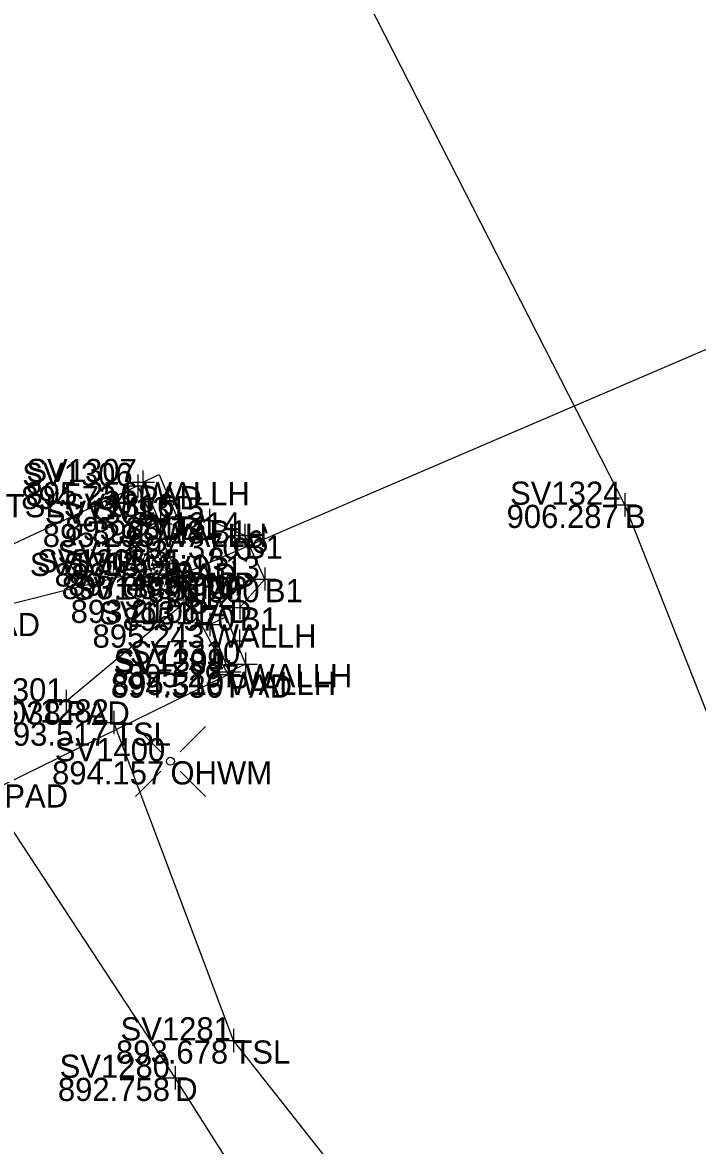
# Model space of a CAD drawing. Extents: x 1918148 to 1919797, y 624701 to 627089.
# Drawn here: x 1918905.66 to 1918934.77, y 625559.4 to 625607.83 of the extents above; entities that cross this region are included whole.
import ezdxf

# ---------------------------------------------------------------- set-up
doc = ezdxf.new("R2010")
doc.units = 0
for name, color, linetype in [('DR_X_Ditch', 7, 'Continuous'), ('DR_X_Elev_Flow', 7, 'Continuous'), ('DR_X_Erosion_Control', 7, 'Continuous'), ('DR_X_Headwall', 7, 'Continuous'), ('DR_X_Storm_Sewer', 7, 'Continuous'), ('DT_X_Break_Line', 7, 'Continuous'), ('SC_Scratch1', 7, 'Continuous'), ('SV_X_Break_Lines', 7, 'Continuous'), ('SV_X_Control_Cells_Found', 7, 'Continuous'), ('SV_X_Shot_Marker', 7, 'Continuous'), ('SV_X_Text_Comment', 7, 'Continuous'), ('SV_X_Text_Elevation', 7, 'Continuous'), ('SV_X_Text_Name', 7, 'Continuous'), ('SV_X_Toe_of_Slope', 7, 'Continuous')]:
    doc.layers.add(name, color=color, linetype=linetype)

msp = doc.modelspace()

# ---------------------------------------------------------------- linework, layer by layer
at = {"layer": 'DR_X_Ditch'}
msp.add_lwpolyline([(1919022.603, 625413.065), (1918990.744, 625447.13), (1918963.473, 625485.28), (1918945.141, 625512.5), (1918919.457, 625550.942), (1918912.249, 625562.326), (1918904.466, 625574.16)], dxfattribs=at)
at = {"layer": 'DR_X_Elev_Flow'}
for p, q in [((1918912.397, 625584.466), (1918912.397, 625583.466)), ((1918912.709, 625584.612), (1918912.709, 625583.612)), ((1918911.897, 625583.966), (1918912.897, 625583.966)), ((1918912.209, 625584.112), (1918913.209, 625584.112)), ((1918912.397, 625583.966), (1918912.397, 625583.966)), ((1918912.709, 625584.112), (1918912.709, 625584.112))]:
    msp.add_line(p, q, dxfattribs=at)
at = {"layer": 'DR_X_Erosion_Control'}
msp.add_lwpolyline([(1918914.537, 625579.717), (1918912.802, 625582.939), (1918912.152, 625584.51), (1918910.641, 625587.846), (1918901.249, 625583.469), (1918899.232, 625582.581), (1918884.997, 625575.988), (1918882.345, 625574.796), (1918883.679, 625571.168), (1918884.991, 625567.785), (1918885.817, 625565.746), (1918890.03, 625568.23), (1918902.973, 625574.056), (1918904.88, 625574.98)], close=True, dxfattribs=at)
at = {"layer": 'DR_X_Headwall'}
for p, q in [((1918910.859, 625588.015), (1918911.556, 625588.347)), ((1918911.556, 625588.347), (1918912.307, 625586.546)), ((1918911.61, 625586.214), (1918910.859, 625588.015)), ((1918912.307, 625586.546), (1918911.61, 625586.214)), ((1918911.61, 625586.214), (1918911.61, 625586.214)), ((1918913.735, 625581.873), (1918914.432, 625582.205)), ((1918914.432, 625582.205), (1918915.276, 625580.164)), ((1918914.579, 625579.832), (1918913.735, 625581.873)), ((1918913.735, 625581.873), (1918913.735, 625581.873)), ((1918913.735, 625581.873), (1918913.735, 625581.873)), ((1918913.735, 625581.873), (1918914.579, 625579.832)), ((1918914.579, 625579.832), (1918913.735, 625581.873)), ((1918915.276, 625580.164), (1918914.579, 625579.832)), ((1918915.276, 625580.164), (1918915.276, 625580.164)), ((1918915.276, 625580.164), (1918915.276, 625580.164)), ((1918914.579, 625579.832), (1918914.579, 625579.832))]:
    msp.add_line(p, q, dxfattribs=at)
at = {"layer": 'DR_X_Storm_Sewer'}
msp.add_line((1918912.397, 625583.966), (1919031.605, 625635.224), dxfattribs=at)
at = {"layer": 'DT_X_Break_Line'}
for p, q in [((1918912.152, 625584.51), (1918903.671, 625582.37)), ((1918912.802, 625582.939), (1918907.541, 625578.556))]:
    msp.add_line(p, q, dxfattribs=at)
at = {"layer": 'SV_X_Break_Lines'}
for points in [[(1919045.664, 625427.604), (1919011.531, 625464.068), (1918983.19, 625498.777), (1918965.767, 625524.183), (1918940.24, 625565.262), (1918931.639, 625587.035), (1918915.781, 625618.093), (1918902.808, 625643.724), (1918894.513, 625661.887), (1918884.61, 625712.489), (1918865.541, 625771.79)], [(1918915.04, 625582.607), (1918916.113, 625583.832), (1918915.252, 625585.709), (1918913.728, 625586.363), (1918912.438, 625586.513)]]:
    msp.add_lwpolyline(points, dxfattribs=at)
at = {"layer": 'SV_X_Control_Cells_Found'}
for p, q in [((1918910.532, 625577.478), (1918911.625, 625576.385)), ((1918912.459, 625576.385), (1918913.55, 625577.478)), ((1918910.532, 625574.46), (1918911.625, 625575.553)), ((1918912.459, 625575.553), (1918913.55, 625574.46))]:
    msp.add_line(p, q, dxfattribs=at)
msp.add_circle((1918912.042, 625575.975), 0.17, dxfattribs=at)
at = {"layer": 'SV_X_Shot_Marker'}
for p, q in [((1918910.641, 625588.346), (1918910.641, 625587.346)), ((1918910.859, 625588.515), (1918910.859, 625587.515)), ((1918910.141, 625587.846), (1918911.141, 625587.846)), ((1918910.359, 625588.015), (1918911.359, 625588.015)), ((1918910.641, 625587.846), (1918910.641, 625587.846)), ((1918910.859, 625588.015), (1918910.859, 625588.015)), ((1918931.639, 625587.535), (1918931.639, 625586.535)), ((1918912.438, 625587.013), (1918912.438, 625586.013)), ((1918913.728, 625586.863), (1918913.728, 625585.863)), ((1918931.139, 625587.035), (1918932.139, 625587.035)), ((1918931.639, 625587.035), (1918931.639, 625587.035)), ((1918911.61, 625586.714), (1918911.61, 625585.714)), ((1918911.938, 625586.513), (1918912.938, 625586.513)), ((1918912.438, 625586.513), (1918912.438, 625586.513)), ((1918913.228, 625586.363), (1918914.228, 625586.363)), ((1918913.728, 625586.363), (1918913.728, 625586.363)), ((1918911.11, 625586.214), (1918912.11, 625586.214)), ((1918911.61, 625586.214), (1918911.61, 625586.214)), ((1918915.252, 625586.209), (1918915.252, 625585.209)), ((1918914.752, 625585.709), (1918915.752, 625585.709)), ((1918915.252, 625585.709), (1918915.252, 625585.709)), ((1918912.152, 625585.01), (1918912.152, 625584.01)), ((1918911.652, 625584.51), (1918912.652, 625584.51)), ((1918912.152, 625584.51), (1918912.152, 625584.51)), ((1918912.397, 625584.466), (1918912.397, 625583.466)), ((1918912.709, 625584.612), (1918912.709, 625583.612)), ((1918911.897, 625583.966), (1918912.897, 625583.966)), ((1918912.209, 625584.112), (1918913.209, 625584.112)), ((1918912.397, 625583.966), (1918912.397, 625583.966)), ((1918912.709, 625584.112), (1918912.709, 625584.112)), ((1918916.113, 625584.332), (1918916.113, 625583.332)), ((1918912.802, 625583.439), (1918912.802, 625582.439)), ((1918915.613, 625583.832), (1918916.613, 625583.832)), ((1918916.113, 625583.832), (1918916.113, 625583.832)), ((1918912.302, 625582.939), (1918913.302, 625582.939)), ((1918912.802, 625582.939), (1918912.802, 625582.939)), ((1918915.04, 625583.107), (1918915.04, 625582.107)), ((1918914.54, 625582.607), (1918915.54, 625582.607)), ((1918915.04, 625582.607), (1918915.04, 625582.607)), ((1918913.735, 625582.373), (1918913.735, 625581.373)), ((1918913.235, 625581.873), (1918914.235, 625581.873)), ((1918913.735, 625581.873), (1918913.735, 625581.873)), ((1918915.021, 625581.662), (1918915.021, 625580.662)), ((1918914.521, 625581.162), (1918915.521, 625581.162)), ((1918915.021, 625581.162), (1918915.021, 625581.162)), ((1918915.276, 625580.664), (1918915.276, 625579.664)), ((1918914.537, 625580.217), (1918914.537, 625579.217)), ((1918914.579, 625580.332), (1918914.579, 625579.332)), ((1918914.776, 625580.164), (1918915.776, 625580.164)), ((1918915.276, 625580.164), (1918915.276, 625580.164)), ((1918914.037, 625579.717), (1918915.037, 625579.717)), ((1918914.079, 625579.832), (1918915.079, 625579.832)), ((1918914.537, 625579.717), (1918914.537, 625579.717)), ((1918914.579, 625579.832), (1918914.579, 625579.832)), ((1918907.541, 625579.056), (1918907.541, 625578.056)), ((1918907.041, 625578.556), (1918908.041, 625578.556)), ((1918907.541, 625578.556), (1918907.541, 625578.556)), ((1918909.609, 625578.144), (1918909.609, 625577.144)), ((1918909.109, 625577.644), (1918910.109, 625577.644)), ((1918909.609, 625577.644), (1918909.609, 625577.644)), ((1918914.755, 625564.436), (1918914.755, 625563.436)), ((1918914.255, 625563.936), (1918915.255, 625563.936)), ((1918914.755, 625563.936), (1918914.755, 625563.936)), ((1918912.249, 625562.826), (1918912.249, 625561.826)), ((1918911.749, 625562.326), (1918912.749, 625562.326)), ((1918912.249, 625562.326), (1918912.249, 625562.326))]:
    msp.add_line(p, q, dxfattribs=at)
at = {"layer": 'SV_X_Toe_of_Slope'}
msp.add_lwpolyline([(1919029.642, 625418.083), (1918993.831, 625449.983), (1918967.662, 625488.104), (1918949.312, 625515.089), (1918923.03, 625553.45), (1918914.755, 625563.936), (1918909.609, 625577.644)], dxfattribs=at)

# ---------------------------------------------------------------- texts
at = {"layer": 'SC_Scratch1'}
msp.add_text("893.06'", height=1, rotation=23.2671, dxfattribs=at).set_placement((1918912.595, 625583.507))
at = {"layer": 'SV_X_Text_Comment'}
for s, p in [('PAD', (1918910.641, 625586.846)), ('WALLH', (1918910.859, 625587.015)), ('TSL', (1918904.941, 625586.498)), ('B', (1918931.639, 625586.035)), ('B1', (1918912.438, 625585.513)), ('B1', (1918913.728, 625585.363)), ('WALLH', (1918911.61, 625585.214)), ('B1', (1918915.252, 625584.709)), ('PAD', (1918912.152, 625583.51)), ('CMP', (1918912.397, 625582.966)), ('PIO', (1918912.397, 625582.966)), ('CMP', (1918912.709, 625583.112)), ('PIO', (1918912.709, 625583.112)), ('B1', (1918916.113, 625582.832)), ('PAD', (1918912.802, 625581.939)), ('B1', (1918915.04, 625581.607)), ('PAD', (1918903.671, 625581.37)), ('WALLH', (1918913.735, 625580.873)), ('WALLH', (1918915.276, 625579.164)), ('WALLH', (1918914.579, 625578.832)), ('PAD', (1918914.537, 625578.717)), ('PAD', (1918907.541, 625577.556)), ('TSL', (1918909.609, 625576.644)), ('OHWM', (1918912.042, 625574.975)), ('PAD', (1918904.88, 625573.98)), ('TSL', (1918914.755, 625562.936)), ('D', (1918912.249, 625561.326))]:
    msp.add_text(s, height=1, dxfattribs=at).set_placement(p)
at = {"layer": 'SV_X_Text_Elevation'}
for s, p in [('894.734', (1918905.61, 625586.846)), ('895.256', (1918905.795, 625587.015)), ('906.287', (1918926.536, 625586.035)), ('895.881', (1918907.497, 625585.513)), ('896.718', (1918908.669, 625585.363)), ('895.295', (1918906.539, 625585.214)), ('897.370', (1918910.191, 625584.709)), ('893.127', (1918907.049, 625583.51)), ('893.059', (1918907.356, 625582.966)), ('893.059', (1918907.356, 625582.966)), ('897.455', (1918907.638, 625583.112)), ('897.455', (1918907.638, 625583.112)), ('896.900', (1918911.052, 625582.832)), ('893.210', (1918907.741, 625581.939)), ('895.970', (1918909.979, 625581.607)), ('895.243', (1918908.685, 625580.873)), ('895.297', (1918910.173, 625579.164)), ('894.536', (1918909.473, 625578.717)), ('895.310', (1918909.518, 625578.832)), ('893.038', (1918902.482, 625577.556)), ('893.517', (1918904.506, 625576.644)), ('894.157', (1918906.939, 625574.975)), ('893.678', (1918909.696, 625562.936)), ('892.758', (1918907.19, 625561.326))]:
    msp.add_text(s, height=1, dxfattribs=at).set_placement(p)
at = {"layer": 'SV_X_Text_Name'}
for s, p in [('SV1306', (1918905.654, 625587.846)), ('SV1307', (1918905.833, 625588.015)), ('SV1324', (1918926.685, 625587.035)), ('SV1316', (1918907.451, 625586.513)), ('SV1315', (1918908.734, 625586.363)), ('SV1308', (1918906.628, 625586.214)), ('SV1314', (1918910.298, 625585.709)), ('SV1303', (1918907.179, 625584.51)), ('SV1304_1', (1918905.98, 625583.966)), ('SV1305_1', (1918906.292, 625584.112)), ('SV1304', (1918907.443, 625583.966)), ('SV1305', (1918907.715, 625584.112)), ('SV1313', (1918911.14, 625583.832)), ('SV1302', (1918907.823, 625582.939)), ('SV1312', (1918910.061, 625582.607)), ('SV1311', (1918908.975, 625581.873)), ('SV1310', (1918910.292, 625580.164)), ('SV1284', (1918909.583, 625579.717)), ('SV1309', (1918909.615, 625579.832)), ('SV1301', (1918902.677, 625578.556)), ('SV1282', (1918904.63, 625577.644)), ('SV1400', (1918907.058, 625575.975)), ('SV1281', (1918909.891, 625563.936)), ('SV1280', (1918907.265, 625562.326))]:
    msp.add_text(s, height=1, dxfattribs=at).set_placement(p)

doc.saveas('drawing.dxf')
